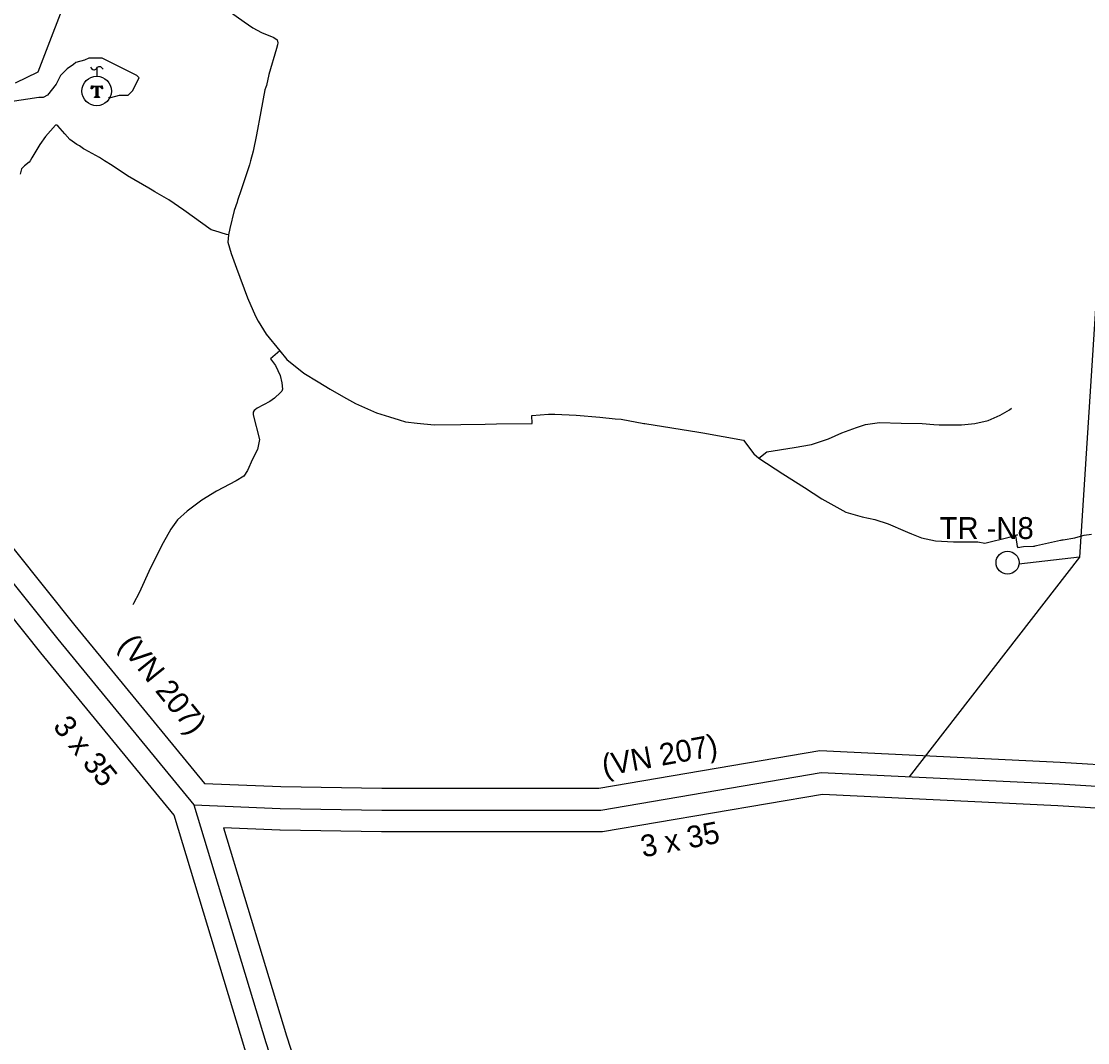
# Model space of a CAD drawing. Extents: x -439095 to -431527, y -1129525 to -1119219.
# Drawn here: x -437672.9 to -437184.8, y -1124403.8 to -1123936.2 of the extents above; entities that cross this region are included whole.
import ezdxf

# ---------------------------------------------------------------- set-up
doc = ezdxf.new("R2010")
doc.units = 0
for name, color, linetype in [('Hranice reseneho uzemi', 7, 'Continuous'), ('UZEMNI REZERVA', 7, 'Continuous'), ('Vrstva 13', 7, 'Continuous'), ('Vrstva 19', 7, 'Continuous'), ('Vrstva 21', 7, 'Continuous'), ('Vrstva 57', 7, 'Continuous'), ('Vrstva 58', 7, 'Continuous'), ('ZU', 7, 'Continuous')]:
    doc.layers.add(name, color=color, linetype=linetype)

msp = doc.modelspace()

# ---------------------------------------------------------------- linework, layer by layer
at = {"layer": 'Hranice reseneho uzemi'}
msp.add_line((-437188.49, -1124181.49), (-437216.29, -1124184.71), dxfattribs=at)
for points in [[(-437129.37, -1123686.51), (-437093.81, -1123746.85), (-437142.42, -1123876.3), (-437179.57, -1124041.51), (-437188.49, -1124181.49), (-437266.5, -1124282.08)], [(-438263.63, -1123828.96), (-438072.97, -1123875.97), (-437977.31, -1123900.59), (-437935.03, -1123912.96), (-437886.52, -1123939.93), (-437886.48, -1123940.09), (-437848.4, -1123976.82), (-437836.05, -1123992.37), (-437836.05, -1123992.37), (-437821.56, -1124011.34), (-437777.52, -1124066.05), (-437725.21, -1124132.8), (-437656.19, -1124219.09), (-437594.04, -1124294.91), (-437554.42, -1124296.58), (-437554.42, -1124296.58), (-437507.95, -1124297.38), (-437407.71, -1124297.33), (-437306.88, -1124280.12), (-437197.9, -1124285.4), (-437107.85, -1124290.93)], [(-437594.04, -1124294.91), (-437561.06, -1124403.71), (-437532.02, -1124493.84), (-437512.18, -1124558.05), (-437465.26, -1124644.76), (-437423.07, -1124724.23), (-437376.49, -1124809.95), (-437340.25, -1124878.04), (-437300.21, -1124952.35), (-437264.2, -1125019.77), (-437218.58, -1125105.97), (-437178.17, -1125179.18), (-437127.47, -1125244.74), (-437060.46, -1125309.51), (-436996.4, -1125371.43), (-436937.2, -1125428.24), (-436916.22, -1125475.49), (-436894.84, -1125522.87), (-436894.84, -1125522.87), (-436875.66, -1125567.39), (-436875.41, -1125567.39), (-436875.41, -1125567.49)]]:
    msp.add_lwpolyline(points, dxfattribs=at)
at = {"layer": 'UZEMNI REZERVA'}
for points in [[(-437675.59, -1123964.37), (-437665.26, -1123959.36), (-437659.16, -1123943.4), (-437650.52, -1123921.14)], [(-437580.82, -1123929.39), (-437570.87, -1123936.44), (-437566.9, -1123939.22), (-437563.06, -1123941.33), (-437557.43, -1123943.56), (-437555.77, -1123944.64), (-437555.48, -1123945.98), (-437555.67, -1123946.98), (-437556.17, -1123948.64), (-437556.17, -1123948.65), (-437559.72, -1123960.55), (-437560.79, -1123965.6), (-437561.01, -1123966.28), (-437561.46, -1123967.57), (-437563.35, -1123977.55), (-437565.32, -1123988.15), (-437566.82, -1123995.6), (-437567.98, -1124000), (-437568.49, -1124001.95), (-437572.25, -1124013.41), (-437573.93, -1124018.29), (-437574.15, -1124018.94), (-437575.5, -1124022.86), (-437577.52, -1124031.05), (-437578.14, -1124034), (-437578.47, -1124037.38), (-437576.87, -1124042.48), (-437574.38, -1124049.22), (-437569.35, -1124062.86), (-437565.68, -1124071.2), (-437564.57, -1124073.43), (-437560.89, -1124079.39), (-437554.64, -1124087.09), (-437551.4, -1124091.07), (-437543.66, -1124097.29), (-437537.02, -1124101.28), (-437531.58, -1124104.55), (-437525.45, -1124108.1), (-437520.03, -1124111.24), (-437510.3, -1124115.46), (-437504.38, -1124117.34), (-437500, -1124118.72), (-437497.13, -1124119.64), (-437491.79, -1124120.17), (-437484.03, -1124120.94), (-437471.79, -1124120.74), (-437460.64, -1124120.58), (-437455.45, -1124120.5), (-437439.06, -1124120.27), (-437439.21, -1124116.69), (-437431.55, -1124115.99), (-437428.77, -1124116.11), (-437418.98, -1124116.52), (-437408.07, -1124117.51), (-437401.06, -1124118.14), (-437401.05, -1124118.14), (-437398.31, -1124118.39), (-437387.92, -1124120.37), (-437387.53, -1124120.41), (-437362.82, -1124124.3), (-437360.93, -1124124.6), (-437342.43, -1124127.91), (-437337.62, -1124134.26), (-437335.4, -1124136.22), (-437324.32, -1124143.35), (-437314.51, -1124149.66), (-437306.44, -1124154.85), (-437295.53, -1124160.98), (-437287.98, -1124163.11), (-437282.21, -1124164.34), (-437276.11, -1124166.25), (-437268.28, -1124169.59), (-437267.25, -1124170.02), (-437265.42, -1124170.82), (-437260.93, -1124172.75), (-437254.44, -1124174.08), (-437246.27, -1124174.47), (-437235.07, -1124174.55), (-437231.89, -1124175.13), (-437220.77, -1124172.36), (-437218.02, -1124171.64), (-437216.92, -1124171.35), (-437218.02, -1124171.64), (-437217.75, -1124172.6), (-437217.02, -1124176.69), (-437216.82, -1124177.16), (-437214.12, -1124176.6), (-437209.54, -1124176.55), (-437209.18, -1124176.49), (-437209.19, -1124176.43), (-437208.81, -1124176.35), (-437208.16, -1124176.21), (-437197.3, -1124173.79), (-437196.9, -1124173.72), (-437196.45, -1124173.59), (-437196.38, -1124173.59), (-437196.34, -1124173.67), (-437195.98, -1124173.59), (-437190.68, -1124172.66), (-437190.2, -1124172.49), (-437186.38, -1124171.48), (-437183.09, -1124170.94)], [(-437578.14, -1124034), (-437579.08, -1124033.73), (-437584.35, -1124032.14), (-437586.04, -1124031.63), (-437598.57, -1124022.6), (-437605.41, -1124017.87), (-437611.85, -1124014.28), (-437613.07, -1124013.56), (-437614.6, -1124012.66), (-437624.42, -1124006.88), (-437631.44, -1124002.14), (-437634.81, -1124000), (-437637.18, -1123998.5), (-437643.89, -1123994.94), (-437644.43, -1123994.56), (-437646.37, -1123993.27), (-437647.54, -1123992.56), (-437650.79, -1123990.23), (-437652.99, -1123987.72), (-437656.2, -1123983.98), (-437656.65, -1123983.7), (-437657.29, -1123983.8), (-437661.87, -1123988.86), (-437664.55, -1123992.66), (-437666.71, -1123996.38), (-437668.07, -1123998.66), (-437668.96, -1124000), (-437669.43, -1124000.71), (-437671.55, -1124002.34), (-437672.94, -1124003.8), (-437673.47, -1124006.25)], [(-437554.64, -1124087.09), (-437558.9, -1124090.67), (-437556.63, -1124093.71), (-437554.43, -1124098.38), (-437553.67, -1124101.71), (-437553.36, -1124104.68), (-437553.73, -1124105.54), (-437554.27, -1124106.12), (-437557.07, -1124108.77), (-437559.22, -1124110.3), (-437564.92, -1124113.25), (-437565.69, -1124113.9), (-437566.29, -1124114.41), (-437566.81, -1124115.22), (-437566.84, -1124116.4), (-437563.88, -1124127.71), (-437564.77, -1124132.18), (-437567.06, -1124136.68), (-437569.47, -1124141.82), (-437571.1, -1124144.49), (-437574.59, -1124146.64), (-437583.66, -1124151.25), (-437590.39, -1124155.5), (-437597.05, -1124160.55), (-437601.53, -1124164.48), (-437604.54, -1124168.76), (-437608.09, -1124175.03), (-437613.88, -1124186.43), (-437619.06, -1124197.81), (-437621.57, -1124202.74), (-437621.89, -1124203.44)], [(-437335.4, -1124136.22), (-437331.62, -1124133.29), (-437319.13, -1124131.29), (-437311.24, -1124130), (-437303.51, -1124127.39), (-437297.32, -1124124.64), (-437290.69, -1124122.11), (-437288.76, -1124121.49), (-437286.56, -1124120.83), (-437280.12, -1124119.89), (-437270.14, -1124120.12), (-437260.59, -1124120.37), (-437255.27, -1124120.75), (-437252.84, -1124120.92), (-437242.64, -1124120.92), (-437236.53, -1124120.28), (-437230.3, -1124118.97), (-437224.91, -1124116.58), (-437220.66, -1124114.09), (-437220.55, -1124114.03), (-437219.65, -1124113.29)]]:
    msp.add_lwpolyline(points, dxfattribs=at)
at = {"layer": 'Vrstva 19'}
msp.add_circle((-437221.49, -1124184.03), 5.25, dxfattribs=at)
at = {"layer": 'Vrstva 57'}
for p, q in [((-437638.43, -1123957.62), (-437638.43, -1123961.37)), ((-437640.51, -1123966.94), (-437640.85, -1123966.6)), ((-437640.17, -1123966.57), (-437640.79, -1123965.96)), ((-437639.83, -1123966.21), (-437640.15, -1123965.88)), ((-437639.12, -1123966.21), (-437639.45, -1123965.88)), ((-437637.98, -1123966.64), (-437638.74, -1123965.88)), ((-437637.98, -1123967.35), (-437638.71, -1123966.62)), ((-437637.98, -1123968.06), (-437638.71, -1123967.33)), ((-437637.98, -1123968.76), (-437638.71, -1123968.04)), ((-437637.98, -1123969.47), (-437638.71, -1123968.74)), ((-437637.98, -1123970.18), (-437638.71, -1123969.45)), ((-437637.7, -1123966.21), (-437638.03, -1123965.88)), ((-437637, -1123966.21), (-437637.32, -1123965.88)), ((-437635.83, -1123966.67), (-437636.62, -1123965.88)), ((-437635.91, -1123965.88), (-437636.02, -1123965.77)), ((-437639.16, -1123971.12), (-437639.39, -1123970.89)), ((-437638.45, -1123971.12), (-437639, -1123970.57)), ((-437637.74, -1123971.12), (-437638.71, -1123970.16))]:
    msp.add_line(p, q, dxfattribs=at)
msp.add_lwpolyline([(-437641.34, -1123957.18), (-437640.83, -1123957.81), (-437640.17, -1123958.31), (-437639.78, -1123958.43), (-437639.38, -1123958.36), (-437638.86, -1123958.05), (-437638.43, -1123957.62), (-437638.01, -1123957.19), (-437637.49, -1123956.88), (-437637.09, -1123956.81), (-437636.7, -1123956.93), (-437636.04, -1123957.43), (-437635.53, -1123958.07)], dxfattribs=at)
msp.add_lwpolyline([(-437635.92, -1123965.77), (-437635.78, -1123967.16), (-437635.96, -1123967.16), (-437636.84, -1123966.21), (-437637.98, -1123966.21), (-437637.98, -1123970.33), (-437637.23, -1123970.94), (-437637.23, -1123971.12), (-437639.45, -1123971.12), (-437639.45, -1123970.94), (-437638.71, -1123970.33), (-437638.71, -1123966.21), (-437639.85, -1123966.21), (-437640.72, -1123967.16), (-437640.91, -1123967.16), (-437640.77, -1123965.77), (-437640.58, -1123965.77), (-437640.26, -1123965.88), (-437636.43, -1123965.88), (-437636.11, -1123965.77)], close=True, dxfattribs=at)
msp.add_circle((-437638.43, -1123968.12), 6.75, dxfattribs=at)
at = {"layer": 'Vrstva 58'}
msp.add_lwpolyline([(-437633, -1123971), (-437632, -1123971), (-437628, -1123970), (-437624, -1123970), (-437623, -1123969), (-437622, -1123968), (-437619, -1123962), (-437620, -1123961), (-437632, -1123955), (-437636, -1123953), (-437638, -1123953), (-437640, -1123953), (-437642, -1123953), (-437644, -1123954), (-437648, -1123955), (-437649, -1123956), (-437652, -1123958), (-437655, -1123961), (-437657, -1123965), (-437661, -1123970), (-437661, -1123970), (-437663, -1123971), (-437665, -1123971), (-437678, -1123973)], dxfattribs=at)
at = {"layer": 'ZU'}
for points in [[(-437603.03, -1124299.71), (-437663.96, -1124225.38), (-437733.05, -1124139.01), (-437785.35, -1124072.27), (-437829.43, -1124017.51), (-437843.94, -1123998.52), (-437855.82, -1123983.56), (-437873.56, -1123966.44)], [(-437793.3, -1124030.5), (-437769.69, -1124059.83), (-437717.37, -1124126.59), (-437648.42, -1124212.8), (-437589.14, -1124285.11), (-437554.13, -1124286.58), (-437507.87, -1124287.38), (-437408.56, -1124287.33), (-437307.49, -1124270.08), (-437197.35, -1124275.41), (-437107.23, -1124280.95), (-436998.91, -1124287.85), (-436905.81, -1124293.56), (-436805.64, -1124300.19), (-436734.95, -1124304.81)], [(-436613.25, -1124332.22), (-436699.78, -1124327.15), (-436806.96, -1124320.15), (-436907.09, -1124313.52), (-437000.15, -1124307.81), (-437108.47, -1124300.91), (-437198.45, -1124295.39), (-437306.27, -1124290.16), (-437406.86, -1124307.33), (-437508.03, -1124307.38), (-437554.5, -1124306.58), (-437554.63, -1124306.58), (-437580.38, -1124305.49)], [(-437243, -1125081.2), (-437273.03, -1125024.46), (-437309.02, -1124957.08), (-437349.07, -1124882.76), (-437385.3, -1124814.69), (-437431.88, -1124728.96), (-437474.07, -1124649.48), (-437521.44, -1124561.94), (-437541.56, -1124496.85), (-437570.6, -1124406.69), (-437603.03, -1124299.71)], [(-437580.38, -1124305.49), (-437551.52, -1124400.73), (-437522.48, -1124490.83), (-437502.92, -1124554.16), (-437456.45, -1124640.04), (-437414.26, -1124719.5), (-437367.68, -1124805.21), (-437331.43, -1124873.32), (-437291.4, -1124947.62), (-437255.37, -1125015.08), (-437209.78, -1125101.21), (-437169.79, -1125173.67), (-437120, -1125238.05), (-437053.51, -1125302.32), (-436989.46, -1125364.23), (-436928.86, -1125422.39), (-436907.09, -1125471.4), (-436885.52, -1125519.22), (-436885.49, -1125519.31), (-436877.62, -1125537.58)]]:
    msp.add_lwpolyline(points, dxfattribs=at)

# ---------------------------------------------------------------- texts
at = {"layer": 'Vrstva 13'}
for s, rotation, p in [('(VN 207)', 308.8716, (-437628.8, -1124221.86)), ('3 x 35', 308.8714, (-437658.85, -1124259.19)), ('(VN 207)', 10.3558, (-437406.2, -1124281.91)), ('3 x 35', 10.9321, (-437388.41, -1124319.08))]:
    msp.add_text(s, height=10, rotation=rotation, dxfattribs=at).set_placement(p)
at = {"layer": 'Vrstva 21'}
msp.add_text('TR -N8', height=10, dxfattribs=at).set_placement((-437252.59, -1124173.21))

doc.saveas('drawing.dxf')
